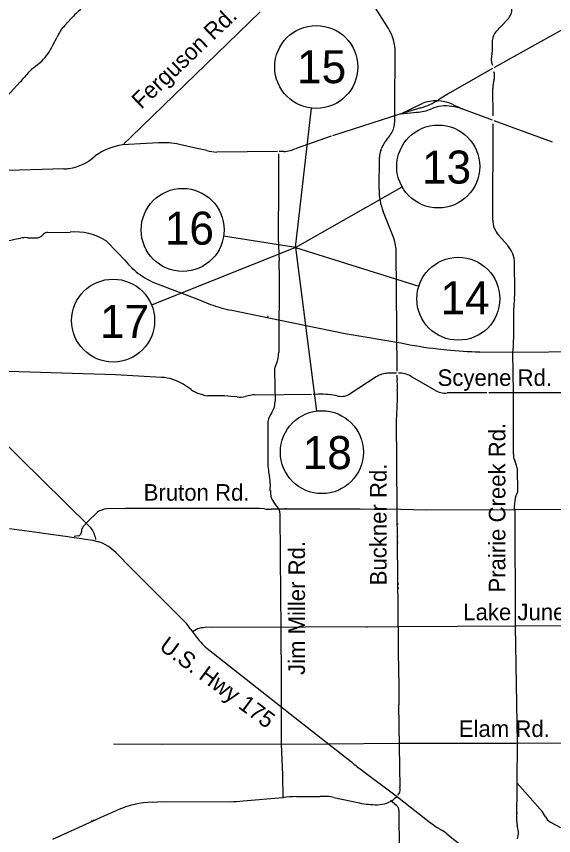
# Model space of a CAD drawing. Extents: x 105094 to 105814, y -291615 to -291123.
# Drawn here: x 105478.5 to 105517.8, y -291508 to -291448 of the extents above; entities that cross this region are included whole.
import ezdxf

# ---------------------------------------------------------------- set-up
doc = ezdxf.new("R2010")
doc.units = 0
doc.layers.add('G_BORDER', color=7, linetype='Continuous')
doc.layers.add('G_MAP', color=7, linetype='Continuous')

msp = doc.modelspace()

# ---------------------------------------------------------------- linework, layer by layer
at = {"layer": 'G_BORDER'}
for q in [(105500.102, -291454.723), (105506.728, -291460.49), (105493.675, -291464.099), (105488.41, -291469.139), (105507.941, -291467.756), (105500.47, -291476.886)]:
    msp.add_line((105498.932, -291464.914), q, dxfattribs=at)
for centre in [(105500.448, -291451.708), (105509.368, -291458.992), (105490.676, -291463.633), (105510.836, -291468.669), (105485.594, -291470.27), (105500.857, -291479.897)]:
    msp.add_circle(centre, 3.035, dxfattribs=at)
at = {"layer": 'G_MAP'}
for p, q in [((105505.719, -291448.885), (105502.663, -291443.988)), ((105482.046, -291448.692), (105482.519, -291448.167)), ((105519.912, -291448.148), (105513.437, -291451.781)), ((105513.574, -291449.126), (105514.453, -291448.212)), ((105513.75, -291448.865), (105513.831, -291448.926)), ((105481.193, -291450.11), (105481.49, -291449.522)), ((105513.346, -291450.373), (105513.337, -291449.727)), ((105506.203, -291454.519), (105506.219, -291450.648)), ((105479.818, -291451.73), (105480.386, -291451.276)), ((105476.701, -291455.077), (105478.804, -291452.8)), ((105513.376, -291455.282), (105513.352, -291453.283)), ((105506.629, -291455.139), (105508.195, -291454.38)), ((105506.2, -291455.525), (105506.199, -291454.519)), ((105508.1, -291454.697), (105506.629, -291455.139)), ((105506.629, -291455.139), (105507.772, -291455.026)), ((105511.147, -291454.778), (105513.317, -291455.569)), ((105506.629, -291455.139), (105501.623, -291456.744)), ((105513.427, -291455.614), (105517.7, -291457.181)), ((105513.36, -291462.912), (105513.372, -291455.879)), ((105501.53, -291456.783), (105498.981, -291457.665)), ((105488.917, -291457.265), (105486.278, -291457.411)), ((105491.75, -291457.664), (105490.44, -291457.38)), ((105492.451, -291457.823), (105491.75, -291457.664)), ((105497.615, -291457.903), (105493.165, -291457.932)), ((105498.077, -291457.897), (105497.732, -291457.9)), ((105505.158, -291457.814), (105505.215, -291457.671)), ((105497.69, -291458.065), (105497.677, -291458.536)), ((105505.036, -291460.653), (105505.06, -291458.32)), ((105481.994, -291459.169), (105473.022, -291459.44)), ((105506.078, -291464.121), (105505.346, -291462.294)), ((105480.35, -291464.079), (105480.499, -291463.942)), ((105480.803, -291463.82), (105482.449, -291463.791)), ((105514.447, -291464.779), (105513.773, -291464.012)), ((105478.519, -291464.288), (105478.823, -291464.246)), ((105479.323, -291464.207), (105479.963, -291464.224)), ((105506.361, -291473.971), (105506.286, -291465.155)), ((105514.971, -291468.099), (105514.951, -291466.093)), ((105497.741, -291466.53), (105497.701, -291472.596)), ((105514.884, -291470.912), (105514.9, -291469.349)), ((105496.895, -291469.921), (105496.889, -291470.008)), ((105509.332, -291472.34), (105509.984, -291472.41)), ((105472.209, -291473.848), (105482.056, -291483.557)), ((105485.766, -291474.249), (105472.483, -291473.813)), ((105497.388, -291473.948), (105497.44, -291476.175)), ((105506.303, -291474.119), (105505.69, -291474.126)), ((105489.137, -291474.423), (105485.766, -291474.249)), ((105504.838, -291474.384), (105502.931, -291475.621)), ((105506.355, -291474.51), (105506.355, -291474.274)), ((105509.116, -291475.356), (105507.34, -291474.326)), ((105491.289, -291475.315), (105490.703, -291474.933)), ((105493.288, -291475.776), (105492.497, -291475.767)), ((105494.67, -291475.859), (105494.196, -291475.815)), ((105495.591, -291475.754), (105495.246, -291475.826)), ((105500.106, -291475.67), (105496.04, -291475.715)), ((105500.594, -291475.657), (105500.222, -291475.667)), ((105512.927, -291475.56), (105510.017, -291475.56)), ((105518.452, -291475.563), (105513.069, -291475.56)), ((105497.197, -291476.998), (105497.114, -291477.121)), ((105506.355, -291484.096), (105506.303, -291477.491)), ((105496.902, -291477.83), (105496.908, -291480.43)), ((105515.096, -291480.885), (105514.958, -291480.504)), ((105515.188, -291482.662), (105515.162, -291481.234)), ((105496.983, -291481.48), (105497.021, -291481.716)), ((105497.073, -291482.204), (105497.054, -291482.727)), ((105515.023, -291483.201), (105515.145, -291482.904)), ((105483.971, -291485.437), (105482.056, -291483.557)), ((105497.548, -291483.835), (105497.316, -291483.511)), ((105484.439, -291484.284), (105483.687, -291485.02)), ((105496.66, -291484.057), (105496.301, -291484.032)), ((105498.233, -291484.106), (105498.233, -291483.999)), ((105506.474, -291496.426), (105506.355, -291484.096)), ((105508.486, -291484.138), (105506.629, -291484.099)), ((105515.026, -291492.612), (105514.994, -291484.121)), ((105478.012, -291485.492), (105480.205, -291485.789)), ((105483.687, -291485.023), (105483.393, -291485.343)), ((105506.313, -291485.139), (105506.426, -291485.139)), ((105480.205, -291485.789), (105480.493, -291485.837)), ((105480.493, -291485.837), (105482.279, -291486.07)), ((105482.279, -291486.07), (105482.563, -291486.121)), ((105482.563, -291486.121), (105483.27, -291486.215)), ((105483.039, -291486.027), (105482.737, -291486.067)), ((105483.28, -291485.698), (105483.209, -291485.931)), ((105506.439, -291486.037), (105506.332, -291486.037)), ((105483.27, -291486.215), (105483.564, -291486.257)), ((105483.564, -291486.257), (105484.116, -291486.344)), ((105484.116, -291486.344), (105484.517, -291486.451)), ((105484.32, -291486.286), (105484.316, -291486.224)), ((105506.332, -291486.518), (105506.445, -291486.508)), ((105485.784, -291487.245), (105486.958, -291488.44)), ((105487.149, -291488.624), (105486.958, -291488.44)), ((105487.149, -291488.624), (105487.975, -291489.461)), ((105487.975, -291489.461), (105488.101, -291489.583)), ((105488.101, -291489.583), (105489.061, -291490.536)), ((105506.364, -291489.535), (105506.487, -291489.535)), ((105506.487, -291489.851), (105506.371, -291489.848)), ((105489.061, -291490.536), (105489.248, -291490.727)), ((105489.248, -291490.727), (105490.74, -291492.212)), ((105504.162, -291492.742), (105504.162, -291492.67)), ((105515.158, -291501.174), (105515.026, -291492.612)), ((105491.269, -291492.877), (105491.405, -291493.058)), ((105491.691, -291492.865), (105491.405, -291493.058)), ((105491.405, -291493.058), (105491.694, -291493.446)), ((105492.574, -291494.351), (105498.878, -291499.307)), ((105506.571, -291504.41), (105506.49, -291498.38)), ((105498.878, -291499.307), (105501.362, -291501.267)), ((105501.362, -291501.267), (105503.021, -291502.566)), ((105503.88, -291503.234), (105506.19, -291504.965)), ((105495.096, -291505.414), (105497.993, -291505.166)), ((105499.01, -291505.101), (105500.738, -291505.095)), ((105501.74, -291505.161), (105503.601, -291505.568)), ((105506.338, -291505.792), (105505.873, -291505.385)), ((105506.19, -291504.965), (105506.509, -291505.214)), ((105506.201, -291505.223), (105506.325, -291505.114)), ((105506.416, -291504.994), (105506.5, -291504.875)), ((105506.509, -291505.214), (105508.802, -291507.019)), ((105484.659, -291506.645), (105484.991, -291506.49)), ((105484.991, -291506.49), (105485.889, -291506.096)), ((105506.522, -291507.026), (105506.498, -291506.129)), ((105515.061, -291506.299), (105515.154, -291506.296)), ((105483.063, -291507.365), (105484.659, -291506.645)), ((105484.081, -291506.974), (105484.032, -291506.864)), ((105484.232, -291506.903), (105484.187, -291506.797)), ((105506.612, -291513.872), (105506.522, -291507.026)), ((105517.584, -291506.98), (105518.368, -291507.384)), ((105481.762, -291507.946), (105483.063, -291507.365)), ((105509.296, -291507.368), (105509.545, -291507.526)), ((105515.194, -291507.417), (105515.145, -291507.241)), ((105481.174, -291508.211), (105481.762, -291507.946)), ((105509.99, -291507.821), (105511.634, -291509.112)), ((105515.165, -291508.209), (105515.214, -291507.962))]:
    msp.add_line(p, q, dxfattribs=at)
for points in [[(105496.336, -291447.662), (105486.88, -291456.847), (105486.383, -291457.341)], [(105513.343, -291451.829), (105510.214, -291453.609), (105509.385, -291454.107)], [(105497.68, -291458.536), (105497.677, -291460.913), (105497.661, -291463.578), (105497.667, -291464.221), (105497.725, -291465.929)], [(105485.075, -291464.44), (105485.899, -291465.257), (105486.441, -291465.842)], [(105488.999, -291467.647), (105491.715, -291468.671), (105492.707, -291469.088)], [(105494.263, -291469.517), (105497.693, -291470.208), (105502.557, -291471.203), (105506.626, -291471.907)], [(105512.391, -291472.579), (105522.503, -291472.527), (105530.354, -291472.56)], [(105514.878, -291480.042), (105514.865, -291475.553), (105514.832, -291472.592)], [(105495.449, -291484.022), (105486.503, -291484.025), (105485.121, -291484.048)], [(105506.629, -291484.099), (105503.649, -291484.073), (105498.426, -291484.061), (105497.144, -291484.064)], [(105519.296, -291484.105), (105514.984, -291484.128), (105508.486, -291484.138)], [(105497.9, -291498.325), (105497.903, -291496.753), (105497.871, -291492.732), (105497.858, -291490.387), (105497.803, -291484.426)], [(105492.846, -291492.719), (105492.422, -291492.713), (105492.177, -291492.748), (105492.022, -291492.759)], [(105531.874, -291492.55), (105515.016, -291492.635), (105506.487, -291492.69), (105492.846, -291492.719)], [(105498.032, -291505.214), (105498.013, -291503.522), (105497.916, -291501.268), (105497.9, -291498.325)], [(105531.916, -291501.203), (105519.379, -291501.187), (105515.038, -291501.209), (105506.545, -291501.232), (105501.303, -291501.268)], [(105515.107, -291506.948), (105515.145, -291504.042), (105515.158, -291501.174)], [(105501.303, -291501.268), (105489.183, -291501.284), (105485.631, -291501.271)], [(105515.144, -291504.125), (105516.827, -291506.018), (105516.909, -291506.12)], [(105488.469, -291505.514), (105489.209, -291505.469), (105494.147, -291505.479)]]:
    msp.add_lwpolyline(points, dxfattribs=at)
for centre, radius, start, end in [((105486.614, -291451.853), 5.51, 127.87873, 138.00905), ((105513.677, -291447.465), 1.078, 316.09537, 1.2822), ((105483.813, -291450.476), 2.511, 134.73837, 157.67579), ((105502.929, -291450.628), 3.29, 359.64852, 31.99263), ((105514.185, -291449.714), 0.848, 136.09798, 180.83333), ((105476.887, -291447.991), 4.799, 316.79964, 333.79355), ((105514.671, -291451.104), 1.428, 164.76641, 199.35484), ((105512.282, -291450.396), 1.065, 341.81155, 1.26611), ((105482.425, -291454.99), 4.174, 128.65847, 142.43397), ((105472.004, -291446.512), 9.262, 317.24429, 320.16842), ((105515.53, -291453.26), 2.178, 162.6913, 180.60261), ((105512.59, -291452.344), 0.902, 342.68457, 18.87784), ((105506.58, -291449.693), 5.23, 286.89442, 302.43068), ((105509.227, -291457.054), 2.868, 65.91589, 111.05513), ((105507.633, -291451.862), 3.167, 272.66457, 293.00616), ((105509.918, -291457.12), 2.565, 80.39231, 114.08895), ((105508.153, -291465.77), 11.393, 74.7656, 78.90316), ((105517.494, -291439.897), 16.177, 243.98374, 246.90164), ((105503.773, -291455.57), 2.427, 343.72305, 1.05453), ((105503.223, -291454.937), 3.166, 319.10548, 335.48143), ((105487.048, -291462.231), 4.881, 99.07624, 124.40418), ((105489.262, -291462.839), 5.584, 77.81596, 93.54671), ((105507.352, -291458.513), 2.298, 139.10767, 158.49483), ((105493.198, -291455.343), 2.589, 253.23527, 269.2678), ((105497.769, -291454.823), 3.09, 275.72876, 293.11018), ((105506.471, -291458.331), 1.411, 158.50106, 179.56765), ((105481.888, -291455.681), 3.487, 278.15483, 313.48891), ((105482.019, -291457.314), 1.855, 269.21711, 281.25719), ((105509.353, -291460.687), 4.317, 179.53931, 201.84748), ((105515.021, -291462.915), 1.662, 179.91358, 221.32797), ((105480.811, -291464.281), 0.461, 90.99693, 132.56801), ((105482.825, -291467.905), 4.131, 57.00286, 95.22042), ((105477.582, -291460.919), 3.497, 271.91429, 285.54347), ((105479.175, -291465.541), 1.342, 83.64266, 105.21125), ((105479.977, -291463.673), 0.551, 268.55583, 312.52766), ((105503.391, -291465.2), 2.895, 0.89031, 21.88194), ((105512.922, -291466.118), 2.03, 0.70401, 41.27859), ((105490.805, -291462.374), 5.574, 218.4726, 251.09484), ((105491.418, -291466.399), 6.325, 358.81856, 4.26411), ((105510.598, -291468.156), 4.373, 352.37832, 0.75082), ((105517.593, -291469.183), 2.698, 170.449, 183.52544), ((105497.222, -291455.759), 14.072, 251.28385, 257.86227), ((105496.827, -291471.198), 18.06, 355.57193, 0.90428), ((105513.375, -291438.378), 34.202, 258.61844, 263.21106), ((105512.734, -291445.905), 26.647, 264.0766, 269.27598), ((105495.24, -291472.547), 2.461, 334.55901, 358.8616), ((105498.144, -291473.933), 0.757, 154.2915, 181.15204), ((105505.708, -291475.724), 1.598, 90.62404, 122.98257), ((105506.561, -291475.668), 1.551, 59.84043, 93.56284), ((105488.974, -291477.585), 3.166, 56.896, 87.04454), ((105513.964, -291474.752), 7.613, 178.17813, 184.47811), ((105492.819, -291473.066), 2.72, 235.76224, 263.19169), ((105501.5, -291475.828), 4.898, 352.1165, 5.63835), ((105509.835, -291474.271), 1.302, 236.49984, 278.05156), ((105493.405, -291483.687), 7.911, 84.26458, 90.84683), ((105494.848, -291473.918), 1.949, 264.75793, 281.79198), ((105495.898, -291476.696), 0.991, 81.792, 108.0762), ((105500.759, -291481.8), 6.145, 77.99781, 91.53466), ((105502.28, -291474.62), 1.194, 258.24257, 303.00824), ((105496.035, -291476.209), 1.405, 325.82004, 1.37338), ((105515.585, -291477.449), 9.283, 174.12934, 180.25644), ((105498.134, -291477.813), 1.232, 145.84655, 180.80199), ((105515.527, -291480.167), 0.661, 169.13842, 210.69461), ((105501.91, -291480.604), 5.005, 178.0139, 190.08312), ((105514.068, -291481.261), 1.095, 1.43857, 20.13197), ((105495.519, -291482.122), 1.556, 356.98261, 15.1136), ((105498.258, -291482.836), 1.159, 173.96762, 215.61519), ((105519.309, -291484.133), 4.386, 167.73425, 180.14556), ((105514.615, -291482.685), 0.574, 337.58827, 2.35933), ((105485.366, -291485.861), 1.83, 97.71957, 120.45025), ((105495.719, -291497.82), 13.801, 87.58083, 91.1213), ((105496.943, -291480.95), 3.12, 264.78325, 273.68879), ((105496.951, -291484.443), 0.852, 1.15247, 45.54665), ((105483.988, -291485.728), 0.709, 147.09768, 177.60197), ((105482.417, -291486.587), 1.934, 10.81884, 36.50845), ((105483.005, -291485.771), 0.259, 277.35586, 321.79334), ((105483.486, -291489.503), 3.222, 44.49691, 71.33914), ((105487.674, -291495.196), 4.279, 32.82085, 44.22655), ((105492.07, -291493.475), 0.718, 93.80314, 121.87917), ((105495.517, -291490.609), 4.76, 216.58252, 231.81404), ((105604.351, -291496.597), 97.877, 179.89997, 181.04381), ((105507.482, -291497.72), 6.586, 227.3696, 236.84968), ((105505.933, -291504.55), 0.653, 330.18724, 12.43607), ((105500.175, -291531.492), 26.416, 92.52747, 94.73849), ((105500.966, -291509.224), 4.136, 79.21719, 93.15353), ((105504.943, -291503.797), 1.901, 269.30182, 311.41882), ((105488.605, -291512.132), 6.619, 91.16974, 114.22147), ((105494.02, -291496.606), 8.874, 270.81891, 276.96624), ((105504.834, -291499.828), 5.871, 257.87684, 270.83776), ((105506.027, -291506.147), 0.471, 2.20094, 48.79147), ((105514.97, -291507.682), 2.49, 25.81802, 38.85141), ((105516.089, -291497.222), 12.21, 233.36093, 236.19926), ((105516.183, -291506.957), 1.076, 179.50039, 195.28382), ((105517.969, -291506.233), 0.84, 205.72797, 242.71584), ((105507.953, -291510.415), 3.298, 51.87101, 61.14347), ((105514.068, -291507.731), 1.169, 348.62192, 15.57888)]:
    msp.add_arc(centre, radius, start, end, dxfattribs=at)

# ---------------------------------------------------------------- texts
at = {"layer": 'G_BORDER'}
for s, p in [('15', (105499.041, -291452.894)), ('13', (105508.178, -291460.242)), ('16', (105489.372, -291464.712)), ('14', (105509.536, -291469.809)), ('17', (105484.628, -291471.536)), ('18', (105499.455, -291481.138))]:
    msp.add_text(s, height=2.416, dxfattribs=at).set_placement(p)
at = {"layer": 'G_MAP'}
for s, rotation, p in [('Ferguson Rd.', 43.6217, (105487.646, -291454.843)), ('Prairie Creek Rd.', 90, (105514.277, -291490.172)), ('Buckner Rd.', 90, (105505.589, -291489.644)), ('Jim Miller Rd.', 90, (105499.623, -291496.202)), ('U.S. Hwy 175', 323.42046, (105488.891, -291494.281))]:
    msp.add_text(s, height=1.21107, rotation=rotation, dxfattribs=at).set_placement(p)
for s, height, p in [('Scyene Rd.', 1.2111, (105509.319, -291475.049)), ('Bruton Rd.', 1.2111, (105487.825, -291483.449)), ('Lake June Rd.', 1.21107, (105511.196, -291492.201)), ('Elam Rd.', 1.2111, (105510.869, -291500.743))]:
    msp.add_text(s, height=height, dxfattribs=at).set_placement(p)

doc.saveas('drawing.dxf')
